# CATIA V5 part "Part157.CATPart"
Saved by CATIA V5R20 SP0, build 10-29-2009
Part number: FA 084700-2 comprimido
Revision: ANY
Definition: UNKNOWN
Nomenclature: FA 084700-2 comprimido
Source: Unknown
Bounding box of the stored display mesh (mm): x -2.45 to 2.45, y 0 to 4.72, z -2.45 to 2.45
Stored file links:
  C:\Users\Utente\Desktop\IO LAVORO\3D X SITO CF\CUMSA\3D files FA\FA 105712-20\Part157.CATPart
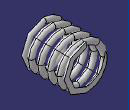
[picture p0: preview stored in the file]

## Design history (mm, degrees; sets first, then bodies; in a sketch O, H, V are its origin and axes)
Body1 "Cortar-Extruir1" (main body)
  Solid1: solid without history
